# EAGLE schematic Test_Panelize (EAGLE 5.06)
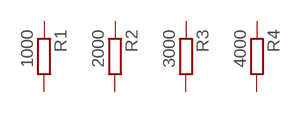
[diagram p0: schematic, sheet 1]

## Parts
R1  1000  R-EU_0207/10  [0207/10]
R2  2000  R-EU_0207/10  [0207/10]
R3  3000  R-EU_0207/10  [0207/10]
R4  4000  R-EU_0207/10  [0207/10]
Unconnected: R1.1 R1.2 R2.1 R2.2 R3.1 R3.2 R4.1 R4.2

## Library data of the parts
R1-R4 = rcl:R-EU_: RESISTOR, European symbol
